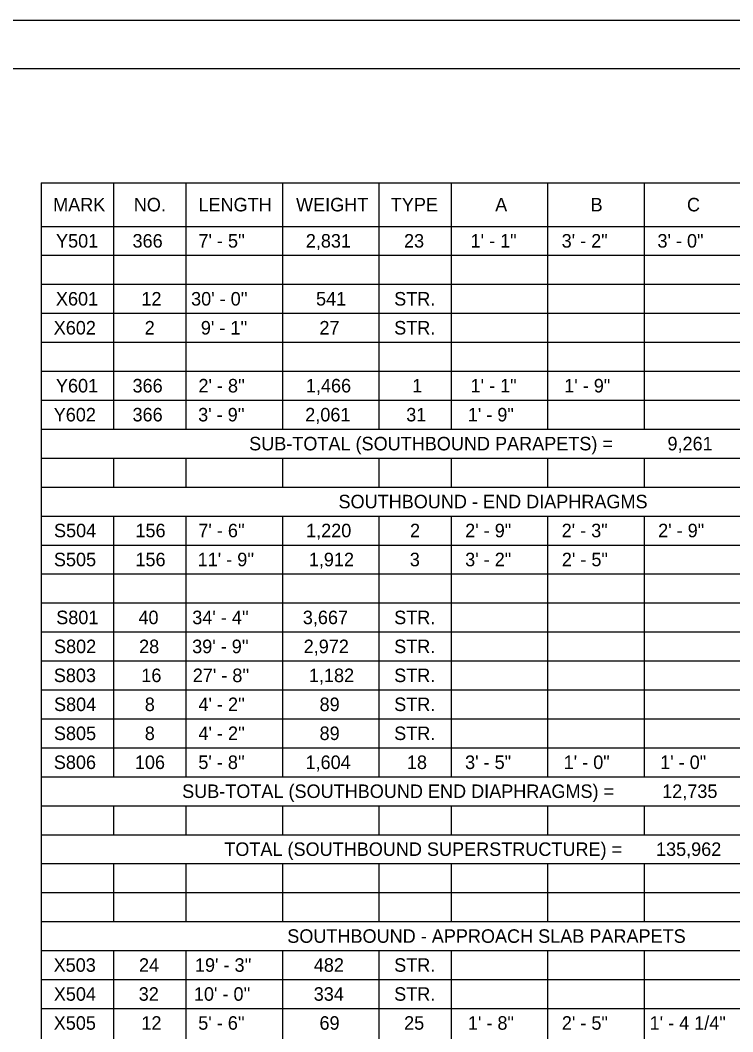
# Model space of a CAD drawing. Extents: x 1485751 to 1485785, y 230696.6 to 230718.6.
# Drawn here: x 1485773.44 to 1485780.83, y 230708.16 to 230718.64 of the extents above; entities that cross this region are included whole.
import ezdxf

# ---------------------------------------------------------------- set-up
doc = ezdxf.new("R2010")
doc.units = 0
for name, color, linetype in [('SH_Border', 7, 'Continuous'), ('SH_Cut_Line', 7, 'Continuous'), ('TX_P_Misc', 7, 'Continuous')]:
    doc.layers.add(name, color=color, linetype=linetype)

msp = doc.modelspace()

# ---------------------------------------------------------------- linework, layer by layer
at = {"layer": 'SH_Border'}
msp.add_lwpolyline([(1485753.033, 230718.141), (1485784.533, 230718.141), (1485784.533, 230697.141), (1485753.033, 230697.141)], close=True, dxfattribs=at)
at = {"layer": 'SH_Cut_Line'}
msp.add_lwpolyline([(1485751.033, 230718.641), (1485785.033, 230718.641), (1485785.033, 230696.641), (1485751.033, 230696.641)], close=True, dxfattribs=at)
at = {"layer": 'TX_P_Misc'}
for p, q in [((1485773.658, 230716.956), (1485782.908, 230716.956)), ((1485773.658, 230716.956), (1485773.658, 230702.406)), ((1485774.408, 230716.956), (1485774.408, 230714.406)), ((1485775.158, 230716.956), (1485775.158, 230714.406)), ((1485776.158, 230716.956), (1485776.158, 230714.406)), ((1485777.158, 230716.956), (1485777.158, 230714.406)), ((1485777.908, 230716.956), (1485777.908, 230714.406)), ((1485778.908, 230716.956), (1485778.908, 230714.406)), ((1485779.908, 230716.956), (1485779.908, 230714.406)), ((1485773.658, 230716.506), (1485782.908, 230716.506)), ((1485773.658, 230716.206), (1485782.908, 230716.206)), ((1485773.658, 230715.906), (1485782.908, 230715.906)), ((1485773.658, 230715.606), (1485782.908, 230715.606)), ((1485773.658, 230715.306), (1485782.908, 230715.306)), ((1485773.658, 230715.006), (1485782.908, 230715.006)), ((1485773.658, 230714.706), (1485782.908, 230714.706)), ((1485773.658, 230714.406), (1485782.908, 230714.406)), ((1485773.658, 230714.106), (1485782.908, 230714.106)), ((1485774.408, 230714.106), (1485774.408, 230713.806)), ((1485775.158, 230714.106), (1485775.158, 230713.806)), ((1485776.158, 230714.106), (1485776.158, 230713.806)), ((1485777.158, 230714.106), (1485777.158, 230713.806)), ((1485777.908, 230714.106), (1485777.908, 230713.806)), ((1485778.908, 230714.106), (1485778.908, 230713.806)), ((1485779.908, 230714.106), (1485779.908, 230713.806)), ((1485773.658, 230713.806), (1485782.908, 230713.806)), ((1485773.658, 230713.506), (1485782.908, 230713.506)), ((1485774.408, 230713.506), (1485774.408, 230710.806)), ((1485775.158, 230713.506), (1485775.158, 230710.806)), ((1485776.158, 230713.506), (1485776.158, 230710.806)), ((1485777.158, 230713.506), (1485777.158, 230710.806)), ((1485777.908, 230713.506), (1485777.908, 230710.806)), ((1485778.908, 230713.506), (1485778.908, 230710.806)), ((1485779.908, 230713.506), (1485779.908, 230710.806)), ((1485773.658, 230713.206), (1485782.908, 230713.206)), ((1485773.658, 230712.906), (1485782.908, 230712.906)), ((1485773.658, 230712.606), (1485782.908, 230712.606)), ((1485773.658, 230712.306), (1485782.908, 230712.306)), ((1485773.658, 230712.006), (1485782.908, 230712.006)), ((1485773.658, 230711.706), (1485782.908, 230711.706)), ((1485773.658, 230711.406), (1485782.908, 230711.406)), ((1485773.658, 230711.106), (1485782.908, 230711.106)), ((1485773.658, 230710.806), (1485782.908, 230710.806)), ((1485773.658, 230710.506), (1485782.908, 230710.506)), ((1485774.408, 230710.506), (1485774.408, 230710.206)), ((1485775.158, 230710.506), (1485775.158, 230710.206)), ((1485776.158, 230710.506), (1485776.158, 230710.206)), ((1485777.158, 230710.506), (1485777.158, 230710.206)), ((1485777.908, 230710.506), (1485777.908, 230710.206)), ((1485778.908, 230710.506), (1485778.908, 230710.206)), ((1485779.908, 230710.506), (1485779.908, 230710.206)), ((1485773.658, 230710.206), (1485782.908, 230710.206)), ((1485773.658, 230709.906), (1485782.908, 230709.906)), ((1485774.408, 230709.906), (1485774.408, 230709.306)), ((1485775.158, 230709.906), (1485775.158, 230709.306)), ((1485776.158, 230709.906), (1485776.158, 230709.306)), ((1485777.158, 230709.906), (1485777.158, 230709.306)), ((1485777.908, 230709.906), (1485777.908, 230709.306)), ((1485778.908, 230709.906), (1485778.908, 230709.306)), ((1485779.908, 230709.906), (1485779.908, 230709.306)), ((1485773.658, 230709.606), (1485782.908, 230709.606)), ((1485773.658, 230709.306), (1485782.908, 230709.306)), ((1485773.658, 230709.006), (1485782.908, 230709.006)), ((1485774.408, 230709.006), (1485774.408, 230703.606)), ((1485775.158, 230709.006), (1485775.158, 230703.606)), ((1485776.158, 230709.006), (1485776.158, 230703.606)), ((1485777.158, 230709.006), (1485777.158, 230703.606)), ((1485777.908, 230709.006), (1485777.908, 230703.606)), ((1485778.908, 230709.006), (1485778.908, 230703.606)), ((1485779.908, 230709.006), (1485779.908, 230703.606)), ((1485773.658, 230708.706), (1485782.908, 230708.706)), ((1485773.658, 230708.406), (1485782.908, 230708.406))]:
    msp.add_line(p, q, dxfattribs=at)

# ---------------------------------------------------------------- texts
for s, p in [('MARK', (1485773.782, 230716.661)), ('NO.', (1485774.618, 230716.661)), ('LENGTH', (1485775.288, 230716.661)), ('WEIGHT', (1485776.3, 230716.661)), ('TYPE', (1485777.282, 230716.661)), ('A', (1485778.364, 230716.661)), ('B', (1485779.353, 230716.661)), ('C', (1485780.352, 230716.661)), ('Y501', (1485773.812, 230716.286)), ('366', (1485774.605, 230716.286)), ("7' - 5''", (1485775.288, 230716.286)), ('2,831', (1485776.401, 230716.286)), ('23', (1485777.419, 230716.286)), ('1\' - 1"', (1485778.109, 230716.286)), ('3\' - 2"', (1485779.053, 230716.286)), ('3\' - 0"', (1485780.046, 230716.286)), ('X601', (1485773.811, 230715.686)), ('12', (1485774.697, 230715.686)), ("30' - 0''", (1485775.212, 230715.686)), ('541', (1485776.507, 230715.686)), ('STR.', (1485777.317, 230715.686)), ('X602', (1485773.788, 230715.386)), ('2', (1485774.731, 230715.386)), ("9' - 1''", (1485775.313, 230715.386)), ('27', (1485776.542, 230715.386)), ('STR.', (1485777.317, 230715.386)), ('Y601', (1485773.811, 230714.786)), ('366', (1485774.605, 230714.786)), ("2' - 8''", (1485775.288, 230714.786)), ('1,466', (1485776.402, 230714.786)), ('1', (1485777.504, 230714.786)), ('1\' - 1"', (1485778.109, 230714.786)), ('1\' - 9"', (1485779.08, 230714.786)), ('Y602', (1485773.788, 230714.486)), ('366', (1485774.605, 230714.486)), ("3' - 9''", (1485775.285, 230714.486)), ('2,061', (1485776.395, 230714.486)), ('31', (1485777.442, 230714.486)), ('1\' - 9"', (1485778.08, 230714.486)), ('SUB-TOTAL (SOUTHBOUND PARAPETS) =', (1485775.814, 230714.186)), ('9,261', (1485780.15, 230714.186)), ('SOUTHBOUND - END DIAPHRAGMS', (1485776.74, 230713.586)), ('S504', (1485773.791, 230713.286)), ('156', (1485774.635, 230713.286)), ("7' - 6''", (1485775.287, 230713.286)), ('1,220', (1485776.404, 230713.286)), ('2', (1485777.481, 230713.286)), ('2\' - 9"', (1485778.053, 230713.286)), ('2\' - 3"', (1485779.053, 230713.286)), ('2\' - 9"', (1485780.053, 230713.286)), ('S505', (1485773.79, 230712.986)), ('156', (1485774.635, 230712.986)), ("11' - 9''", (1485775.28, 230712.986)), ('1,912', (1485776.432, 230712.986)), ('3', (1485777.479, 230712.986)), ('3\' - 2"', (1485778.053, 230712.986)), ('2\' - 5"', (1485779.055, 230712.986)), ('S801', (1485773.814, 230712.386)), ('40', (1485774.666, 230712.386)), ("34' - 4''", (1485775.224, 230712.386)), ('3,667', (1485776.37, 230712.386)), ('STR.', (1485777.317, 230712.386)), ('S802', (1485773.791, 230712.086)), ('28', (1485774.673, 230712.086)), ("39' - 9''", (1485775.223, 230712.086)), ('2,972', (1485776.379, 230712.086)), ('STR.', (1485777.317, 230712.086)), ('S803', (1485773.789, 230711.786)), ('16', (1485774.696, 230711.786)), ("27' - 8''", (1485775.229, 230711.786)), ('1,182', (1485776.433, 230711.786)), ('STR.', (1485777.317, 230711.786)), ('S804', (1485773.791, 230711.486)), ('8', (1485774.732, 230711.486)), ("4' - 2''", (1485775.288, 230711.486)), ('89', (1485776.544, 230711.486)), ('STR.', (1485777.317, 230711.486)), ('S805', (1485773.79, 230711.186)), ('8', (1485774.732, 230711.186)), ("4' - 2''", (1485775.288, 230711.186)), ('89', (1485776.544, 230711.186)), ('STR.', (1485777.317, 230711.186)), ('S806', (1485773.789, 230710.886)), ('106', (1485774.629, 230710.886)), ("5' - 8''", (1485775.287, 230710.886)), ('1,604', (1485776.398, 230710.886)), ('18', (1485777.449, 230710.886)), ('3\' - 5"', (1485778.052, 230710.886)), ('1\' - 0"', (1485779.074, 230710.886)), ('1\' - 0"', (1485780.074, 230710.886)), ('SUB-TOTAL (SOUTHBOUND END DIAPHRAGMS) =', (1485775.119, 230710.586)), ('12,735', (1485780.095, 230710.586)), ('TOTAL (SOUTHBOUND SUPERSTRUCTURE) =', (1485775.556, 230709.986)), ('135,962', (1485780.031, 230709.986)), ('SOUTHBOUND - APPROACH SLAB PARAPETS', (1485776.209, 230709.086)), ('X503', (1485773.787, 230708.786)), ('24', (1485774.672, 230708.786)), ("19' - 3''", (1485775.252, 230708.786)), ('482', (1485776.484, 230708.786)), ('STR.', (1485777.317, 230708.786)), ('X504', (1485773.789, 230708.486)), ('32', (1485774.669, 230708.486)), ("10' - 0''", (1485775.241, 230708.486)), ('334', (1485776.483, 230708.486)), ('STR.', (1485777.317, 230708.486)), ('X505', (1485773.788, 230708.186)), ('12', (1485774.697, 230708.186)), ("5' - 6''", (1485775.286, 230708.186)), ('69', (1485776.543, 230708.186)), ('25', (1485777.42, 230708.186)), ('1\' - 8"', (1485778.081, 230708.186)), ('2\' - 5"', (1485779.055, 230708.186)), ('1\' - 4 1/4"', (1485779.965, 230708.186))]:
    msp.add_text(s, height=0.14, dxfattribs=at).set_placement(p)

doc.saveas('drawing.dxf')
